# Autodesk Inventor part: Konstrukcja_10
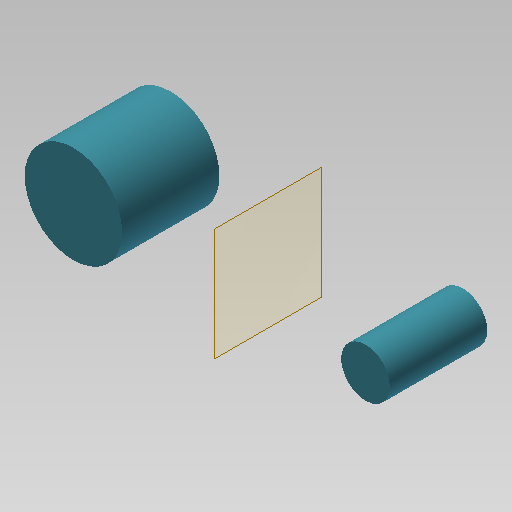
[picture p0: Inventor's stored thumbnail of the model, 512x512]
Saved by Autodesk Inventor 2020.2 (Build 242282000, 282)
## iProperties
Created: 2014-08
Part Number: Konstrukcja_10
Material: Ogólny
Document SubType Name: Modeling
Designer: F.Stasiak
Density: 1 g/cm^3
Appearance: Niebieska z odcieniem szarości
Catalog Web Link: www.expertbooks.pl
Manager: www.cadconsulting.pl
Company: Fabian Stasiak CAD Consulting
Author: F.Stasiak
Subject: Zbiór ćwiczeń. Autodesk Inventor 2020. Kurs Professional
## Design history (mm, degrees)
sketch "Szkic1"
  geometry: L1 (-1500, 0)-(1500, 0); C1 r 500 at (-1500, 0); C2 r 250 at (1500, 0); 2 further points
  constraints: 2 centre point, 2 end point, 1 coincident, 1 horizontal, 1 midpoint
  dimensions: "d0" = 1000 diameter of C1; "d1" = 500 diameter of C2; "d12" = 3000 distance of L1.start L1.end
extrude "Wyciągnięcie proste1" new body sketch "Szkic1" distance "d2" = 1000; taper "d3" = 0 deg
sketch "Szkic2"
  geometry: L1 (2000, 1000)-(1000, 1000) reference; C1 r 32.5 at (1500, 750); 2 further points
  constraints: 1 centre point, 1 midpoint, 1 vertical alignment
  dimensions: "d4" = 65 diameter of C1; "d5" = 250 distance from line of L1 C1.centre
extrude "Wyciągnięcie proste2" join sketch "Szkic2" distance "d6" = 550; taper "d7" = 0 deg
sketch "Szkic3"
  geometry: L1 (-1250, 1000)-(-1750, 1000) reference; C1 r 32.5 at (-1500, 750); 2 further points
  constraints: 1 centre point, 1 midpoint, 1 vertical alignment
  dimensions: "d8" = 65 diameter of C1; "d9" = 250 distance from line of L1 C1.centre
extrude "Wyciągnięcie proste3" join sketch "Szkic3" distance "d10" = 300; taper "d11" = 0 deg
node "Bryła1"
